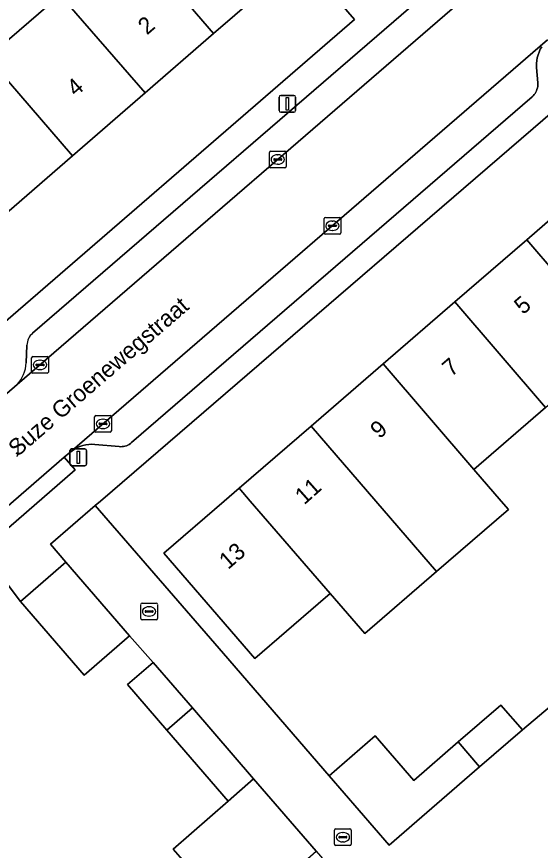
# Model space of a CAD drawing. Extents: x 160304 to 160955, y 383684 to 384161.
# Drawn here: x 160443.23 to 160474.6, y 383979.08 to 384029.01 of the extents above; entities that cross this region are included whole.
import ezdxf

# ---------------------------------------------------------------- set-up
doc = ezdxf.new("R2010")
doc.units = 0
for name, color, linetype in [('IMGEO_Erf', 7, 'Continuous'), ('IMGEO_Kolk', 7, 'Continuous'), ('IMGEO_Lichtmast', 7, 'Continuous'), ('IMGEO_Muur', 7, 'Continuous'), ('IMGEO_Openbare_ruimte_label', 7, 'Continuous'), ('IMGEO_Pand', 7, 'Continuous'), ('IMGEO_Pand_nummerreeks', 7, 'Continuous'), ('IMGEO_Parkeervlak_open', 7, 'Continuous'), ('IMGEO_Rijbaan_lokaal_open', 7, 'Continuous'), ('IMGEO_Rioolput', 7, 'Continuous'), ('IMGEO_Voetpad_open', 7, 'Continuous')]:
    doc.layers.add(name, color=color, linetype=linetype)

msp = doc.modelspace()

# ---------------------------------------------------------------- linework, layer by layer
at = {"layer": 'IMGEO_Erf'}
for points in [[(160423.895, 384030.632), (160426.46, 384027.667), (160424.932, 384026.345), (160440.174, 384008.722), (160463.456, 384028.84), (160460.261, 384032.534), (160455.025, 384028.001), (160450.924, 384024.45), (160446.57, 384020.681), (160442.307, 384016.99), (160437.953, 384013.22), (160432.866, 384019.096), (160436.647, 384022.369), (160437.219, 384022.865), (160441.483, 384026.556), (160445.837, 384030.325)], [(160480.946, 384028.137), (160448.239, 384000), (160447.932, 383999.736), (160455.612, 383990.866), (160461.946, 383983.55), (160464.706, 383985.939), (160467.017, 383983.269), (160469.682, 383985.571), (160472.239, 383987.78), (160473.521, 383986.297), (160476.215, 383988.562)], [(160474.915, 384005.61), (160470.61, 384001.896), (160472.246, 384000), (160472.684, 383999.492), (160468.376, 383995.775), (160464.074, 383992.064), (160462, 383994.468), (160461.279, 383993.846), (160457.495, 383990.577), (160452.051, 383996.881), (160455.662, 384000), (160456.556, 384000.772), (160460.864, 384004.492), (160465.175, 384008.216), (160469.478, 384011.932), (160473.784, 384015.651), (160478.09, 384019.371)], [(160456.376, 383974.841), (160452.604, 383979.153), (160455.89, 383982.028), (160452.212, 383986.286), (160449.864, 383989.004), (160451.404, 383990.334), (160449.988, 383991.923), (160447.265, 383989.57), (160443.455, 383993.98), (160442.593, 383995.12), (160425.555, 383980.472), (160425.435, 383978.53)]]:
    msp.add_lwpolyline(points, dxfattribs=at)
at = {"layer": 'IMGEO_Kolk'}
for p, q in [((160458.367, 384020.029), (160458.367, 384020.881)), ((160458.442, 384020.955), (160459.294, 384020.955)), ((160459.368, 384020.881), (160459.368, 384020.029)), ((160458.626, 384020.449), (160458.626, 384020.461)), ((160459.064, 384020.412), (160458.666, 384020.412)), ((160458.669, 384020.498), (160459.067, 384020.498)), ((160458.855, 384020.735), (160458.88, 384020.735)), ((160459.11, 384020.461), (160459.11, 384020.449)), ((160459.294, 384019.955), (160458.442, 384019.955)), ((160458.878, 384020.175), (160458.853, 384020.175)), ((160461.644, 384016.062), (160461.644, 384016.914)), ((160461.719, 384016.988), (160462.571, 384016.988)), ((160462.645, 384016.914), (160462.645, 384016.062)), ((160461.903, 384016.482), (160461.903, 384016.494)), ((160462.341, 384016.445), (160461.943, 384016.445)), ((160461.946, 384016.531), (160462.344, 384016.531)), ((160462.132, 384016.768), (160462.157, 384016.768)), ((160462.387, 384016.494), (160462.387, 384016.482)), ((160462.571, 384015.988), (160461.719, 384015.988)), ((160462.155, 384016.208), (160462.13, 384016.208)), ((160444.122, 384007.725), (160444.122, 384008.577)), ((160444.197, 384008.651), (160445.049, 384008.651)), ((160444.61, 384008.431), (160444.635, 384008.431)), ((160445.123, 384008.577), (160445.123, 384007.725)), ((160444.381, 384008.145), (160444.381, 384008.157)), ((160444.819, 384008.108), (160444.421, 384008.108)), ((160444.424, 384008.194), (160444.822, 384008.194)), ((160444.633, 384007.871), (160444.608, 384007.871)), ((160444.865, 384008.157), (160444.865, 384008.145)), ((160445.049, 384007.651), (160444.197, 384007.651)), ((160447.897, 384004.196), (160447.897, 384005.048)), ((160447.972, 384005.122), (160448.824, 384005.122)), ((160448.385, 384004.902), (160448.41, 384004.902)), ((160448.898, 384005.048), (160448.898, 384004.196)), ((160448.156, 384004.616), (160448.156, 384004.628)), ((160448.594, 384004.579), (160448.196, 384004.579)), ((160448.199, 384004.665), (160448.597, 384004.665)), ((160448.64, 384004.628), (160448.64, 384004.616)), ((160448.824, 384004.122), (160447.972, 384004.122)), ((160448.408, 384004.342), (160448.383, 384004.342)), ((160450.734, 383993.888), (160451.586, 383993.888)), ((160450.659, 383992.962), (160450.659, 383993.814)), ((160450.918, 383993.382), (160450.918, 383993.394)), ((160450.961, 383993.431), (160451.359, 383993.431)), ((160451.147, 383993.668), (160451.172, 383993.668)), ((160451.402, 383993.394), (160451.402, 383993.382)), ((160451.66, 383993.814), (160451.66, 383992.962)), ((160451.586, 383992.888), (160450.734, 383992.888)), ((160451.356, 383993.345), (160450.958, 383993.345)), ((160451.17, 383993.108), (160451.145, 383993.108)), ((160462.267, 383979.443), (160462.267, 383980.295)), ((160462.342, 383980.369), (160463.194, 383980.369)), ((160462.569, 383979.912), (160462.967, 383979.912)), ((160462.755, 383980.149), (160462.78, 383980.149)), ((160463.268, 383980.295), (160463.268, 383979.443)), ((160462.526, 383979.863), (160462.526, 383979.875)), ((160462.964, 383979.826), (160462.566, 383979.826)), ((160462.778, 383979.589), (160462.753, 383979.589)), ((160463.01, 383979.875), (160463.01, 383979.863)), ((160463.194, 383979.369), (160462.342, 383979.369))]:
    msp.add_line(p, q, dxfattribs=at)
for points in [[(160458.367, 384020.029), (160458.367, 384020.881)], [(160458.442, 384020.955), (160459.294, 384020.955)], [(160459.368, 384020.881), (160459.368, 384020.029)], [(160459.294, 384019.955), (160458.442, 384019.955)], [(160461.644, 384016.062), (160461.644, 384016.914)], [(160461.719, 384016.988), (160462.571, 384016.988)], [(160462.645, 384016.914), (160462.645, 384016.062)], [(160462.571, 384015.988), (160461.719, 384015.988)], [(160444.122, 384007.725), (160444.122, 384008.577)], [(160444.197, 384008.651), (160445.049, 384008.651)], [(160445.123, 384008.577), (160445.123, 384007.725)], [(160445.049, 384007.651), (160444.197, 384007.651)], [(160447.897, 384004.196), (160447.897, 384005.048)], [(160447.972, 384005.122), (160448.824, 384005.122)], [(160448.898, 384005.048), (160448.898, 384004.196)], [(160448.824, 384004.122), (160447.972, 384004.122)], [(160450.734, 383993.888), (160451.586, 383993.888)], [(160450.659, 383992.962), (160450.659, 383993.814)], [(160451.66, 383993.814), (160451.66, 383992.962)], [(160451.586, 383992.888), (160450.734, 383992.888)], [(160462.267, 383979.443), (160462.267, 383980.295)], [(160462.342, 383980.369), (160463.194, 383980.369)], [(160463.268, 383980.295), (160463.268, 383979.443)], [(160463.194, 383979.369), (160462.342, 383979.369)]]:
    msp.add_lwpolyline(points, dxfattribs=at)
for centre, radius, start, end in [((160458.444, 384020.879), 0.0765, 91.552, 178.448), ((160458.444, 384020.879), 0.0765, 91.552, 178.448), ((160459.292, 384020.879), 0.0765, 1.552, 88.448), ((160459.292, 384020.879), 0.0765, 1.552, 88.448), ((160458.666, 384020.458), 0.0403, 85.8775, 175.7526), ((160458.663, 384020.448), 0.0366, 178.938, 274.7102), ((160459.067, 384020.455), 0.043, 264.8664, 352.4533), ((160459.071, 384020.46), 0.0386, 1.7309, 96.639), ((160458.444, 384020.031), 0.0765, 181.552, 268.448), ((160458.444, 384020.031), 0.0765, 181.552, 268.448), ((160459.292, 384020.031), 0.0765, 271.552, 358.448), ((160459.292, 384020.031), 0.0765, 271.552, 358.448), ((160461.721, 384016.912), 0.0765, 91.552, 178.448), ((160461.721, 384016.912), 0.0765, 91.552, 178.448), ((160462.569, 384016.912), 0.0765, 1.552, 88.448), ((160462.569, 384016.912), 0.0765, 1.552, 88.448), ((160461.943, 384016.491), 0.0403, 85.8775, 175.7526), ((160461.94, 384016.481), 0.0366, 178.938, 274.7102), ((160462.344, 384016.488), 0.043, 264.8664, 352.4533), ((160462.348, 384016.493), 0.0386, 1.7309, 96.639), ((160461.721, 384016.064), 0.0765, 181.552, 268.448), ((160461.721, 384016.064), 0.0765, 181.552, 268.448), ((160462.569, 384016.064), 0.0765, 271.552, 358.448), ((160462.569, 384016.064), 0.0765, 271.552, 358.448), ((160444.199, 384008.575), 0.0765, 91.552, 178.448), ((160444.199, 384008.575), 0.0765, 91.552, 178.448), ((160445.047, 384008.575), 0.0765, 1.552, 88.448), ((160445.047, 384008.575), 0.0765, 1.552, 88.448), ((160444.421, 384008.154), 0.0403, 85.8775, 175.7526), ((160444.418, 384008.144), 0.0366, 178.938, 274.7102), ((160444.822, 384008.151), 0.043, 264.8664, 352.4533), ((160444.826, 384008.156), 0.0386, 1.7309, 96.639), ((160444.199, 384007.727), 0.0765, 181.552, 268.448), ((160444.199, 384007.727), 0.0765, 181.552, 268.448), ((160445.047, 384007.727), 0.0765, 271.552, 358.448), ((160445.047, 384007.727), 0.0765, 271.552, 358.448), ((160447.974, 384005.046), 0.0765, 91.552, 178.448), ((160447.974, 384005.046), 0.0765, 91.552, 178.448), ((160448.822, 384005.046), 0.0765, 1.552, 88.448), ((160448.822, 384005.046), 0.0765, 1.552, 88.448), ((160448.196, 384004.625), 0.0403, 85.8775, 175.7526), ((160448.193, 384004.615), 0.0366, 178.938, 274.7102), ((160448.597, 384004.622), 0.043, 264.8664, 352.4533), ((160448.601, 384004.627), 0.0386, 1.7309, 96.639), ((160447.974, 384004.198), 0.0765, 181.552, 268.448), ((160447.974, 384004.198), 0.0765, 181.552, 268.448), ((160448.822, 384004.198), 0.0765, 271.552, 358.448), ((160448.822, 384004.198), 0.0765, 271.552, 358.448), ((160450.736, 383993.812), 0.0765, 91.552, 178.448), ((160450.736, 383993.812), 0.0765, 91.552, 178.448), ((160451.584, 383993.812), 0.0765, 1.552, 88.448), ((160451.584, 383993.812), 0.0765, 1.552, 88.448), ((160450.958, 383993.391), 0.0403, 85.8775, 175.7526), ((160451.363, 383993.393), 0.0386, 1.7309, 96.639), ((160450.736, 383992.964), 0.0765, 181.552, 268.448), ((160450.736, 383992.964), 0.0765, 181.552, 268.448), ((160450.955, 383993.381), 0.0366, 178.938, 274.7102), ((160451.359, 383993.388), 0.043, 264.8664, 352.4533), ((160451.584, 383992.964), 0.0765, 271.552, 358.448), ((160451.584, 383992.964), 0.0765, 271.552, 358.448), ((160462.344, 383980.293), 0.0765, 91.552, 178.448), ((160462.344, 383980.293), 0.0765, 91.552, 178.448), ((160462.566, 383979.872), 0.0403, 85.8775, 175.7526), ((160462.971, 383979.874), 0.0386, 1.7309, 96.639), ((160463.192, 383980.293), 0.0765, 1.552, 88.448), ((160463.192, 383980.293), 0.0765, 1.552, 88.448), ((160462.344, 383979.445), 0.0765, 181.552, 268.448), ((160462.344, 383979.445), 0.0765, 181.552, 268.448), ((160462.563, 383979.862), 0.0366, 178.938, 274.7102), ((160462.967, 383979.869), 0.043, 264.8664, 352.4533), ((160463.192, 383979.445), 0.0765, 271.552, 358.448), ((160463.192, 383979.445), 0.0765, 271.552, 358.448)]:
    msp.add_arc(centre, radius, start, end, dxfattribs=at)
for centre, major_axis, ratio, start_param, end_param in [((160458.854, 384020.455), (-0.387, 0.002), 0.722429, 4.712389, 7.853982), ((160458.879, 384020.455), (-0.39, 0.002), 0.717154, 1.570796, 4.712389), ((160462.131, 384016.488), (-0.387, 0.002), 0.722429, 4.712389, 7.853982), ((160462.156, 384016.488), (-0.39, 0.002), 0.717154, 1.570796, 4.712389), ((160444.609, 384008.151), (-0.387, 0.002), 0.722429, 4.712389, 7.853982), ((160444.634, 384008.151), (-0.39, 0.002), 0.717154, 1.570796, 4.712389), ((160448.384, 384004.622), (-0.387, 0.002), 0.722429, 4.712389, 7.853982), ((160448.409, 384004.622), (-0.39, 0.002), 0.717154, 1.570796, 4.712389), ((160451.146, 383993.388), (-0.387, 0.002), 0.722429, 4.712389, 7.853982), ((160451.171, 383993.388), (-0.39, 0.002), 0.717154, 1.570796, 4.712389), ((160462.754, 383979.869), (-0.387, 0.002), 0.722429, 4.712389, 7.853982), ((160462.779, 383979.869), (-0.39, 0.002), 0.717154, 1.570796, 4.712389)]:
    msp.add_ellipse(centre, major_axis=major_axis, ratio=ratio, start_param=start_param, end_param=end_param, dxfattribs=at)
at = {"layer": 'IMGEO_Lichtmast'}
for p, q in [((160458.948, 384023.389), (160458.948, 384024.189)), ((160458.948, 384024.189), (160458.948, 384023.389)), ((160459.048, 384024.289), (160459.838, 384024.289)), ((160459.838, 384024.289), (160459.048, 384024.289)), ((160459.938, 384024.189), (160459.938, 384023.389)), ((160459.938, 384023.389), (160459.938, 384024.189)), ((160459.838, 384023.289), (160459.048, 384023.289)), ((160459.048, 384023.289), (160459.838, 384023.289)), ((160446.42, 384002.217), (160446.42, 384003.017)), ((160446.42, 384003.017), (160446.42, 384002.217)), ((160446.52, 384003.117), (160447.31, 384003.117)), ((160447.31, 384003.117), (160446.52, 384003.117)), ((160447.41, 384003.017), (160447.41, 384002.217)), ((160447.41, 384002.217), (160447.41, 384003.017)), ((160447.31, 384002.117), (160446.52, 384002.117)), ((160446.52, 384002.117), (160447.31, 384002.117))]:
    msp.add_line(p, q, dxfattribs=at)
for points in [[(160459.368, 384024.164), (160459.518, 384024.164), (160459.518, 384023.414), (160459.368, 384023.414), (160459.368, 384024.164)], [(160446.84, 384002.992), (160446.99, 384002.992), (160446.99, 384002.242), (160446.84, 384002.242), (160446.84, 384002.992)]]:
    msp.add_lwpolyline(points, dxfattribs=at)
for centre, start, end in [((160459.048, 384024.189), 90, 180), ((160459.048, 384024.189), 90, 180), ((160459.838, 384024.189), 0, 90), ((160459.838, 384024.189), 360, 90), ((160459.048, 384023.389), 180, 270), ((160459.048, 384023.389), 180, 270), ((160459.838, 384023.389), 270, 0), ((160459.838, 384023.389), 270, 0), ((160446.52, 384003.017), 90, 180), ((160446.52, 384003.017), 90, 180), ((160447.31, 384003.017), 0, 90), ((160447.31, 384003.017), 360, 90), ((160446.52, 384002.217), 180, 270), ((160446.52, 384002.217), 180, 270), ((160447.31, 384002.217), 270, 0), ((160447.31, 384002.217), 270, 0)]:
    msp.add_arc(centre, 0.1, start, end, dxfattribs=at)
at = {"layer": 'IMGEO_Muur'}
msp.add_lwpolyline([(160461.946, 383983.55), (160455.612, 383990.866)], dxfattribs=at)
at = {"layer": 'IMGEO_Pand'}
for points in [[(160463.097, 384036.252), (160463.23, 384038.097), (160463.324, 384039.406), (160461.083, 384041.994), (160458.283, 384045.229), (160452.287, 384040.18), (160454.4, 384037.739), (160449.944, 384033.881), (160455.025, 384028.001), (160460.261, 384032.534), (160463, 384034.905)], [(160445.837, 384030.325), (160450.924, 384024.45), (160455.025, 384028.001), (160449.944, 384033.881)], [(160445.837, 384030.325), (160441.483, 384026.556), (160446.57, 384020.681), (160450.924, 384024.45)], [(160437.219, 384022.865), (160442.307, 384016.99), (160446.57, 384020.681), (160441.483, 384026.556)], [(160483.531, 384013.043), (160478.09, 384019.371), (160473.784, 384015.651), (160479.25, 384009.3), (160481.518, 384006.62), (160485.849, 384010.356), (160485.647, 384010.59)], [(160481.518, 384006.62), (160479.25, 384009.3), (160473.784, 384015.651), (160469.478, 384011.932), (160474.915, 384005.61), (160477.59, 384007.917), (160479.908, 384005.23)], [(160465.175, 384008.216), (160470.61, 384001.896), (160474.915, 384005.61), (160469.478, 384011.932)], [(160468.376, 383995.775), (160472.684, 383999.492), (160472.246, 384000), (160470.61, 384001.896), (160465.175, 384008.216), (160460.864, 384004.492), (160464.735, 384000)], [(160456.556, 384000.772), (160457.223, 384000), (160462, 383994.468), (160464.074, 383992.064), (160468.376, 383995.775), (160464.735, 384000), (160460.864, 384004.492)], [(160456.556, 384000.772), (160455.662, 384000), (160452.051, 383996.881), (160457.495, 383990.577), (160461.279, 383993.846), (160462, 383994.468), (160457.223, 384000)], [(160446.178, 383996.332), (160443.455, 383993.98), (160447.265, 383989.57), (160449.988, 383991.923)], [(160452.212, 383986.286), (160453.75, 383987.619), (160451.404, 383990.334), (160449.864, 383989.004)], [(160452.212, 383986.286), (160455.89, 383982.028), (160457.423, 383983.369), (160453.75, 383987.619)], [(160469.682, 383985.571), (160470.963, 383984.088), (160473.521, 383986.297), (160472.239, 383987.78)], [(160469.682, 383985.571), (160467.017, 383983.269), (160464.706, 383985.939), (160461.946, 383983.55), (160465.537, 383979.401), (160470.963, 383984.088)], [(160457.423, 383983.369), (160455.89, 383982.028), (160452.604, 383979.153), (160456.376, 383974.841), (160459.641, 383977.685), (160461.178, 383979.024)]]:
    msp.add_lwpolyline(points, close=True, dxfattribs=at)
at = {"layer": 'IMGEO_Parkeervlak_open'}
for points in [[(160443.247, 384006.975), (160471.504, 384031.385)], [(160468.436, 384031.002), (160444.182, 384010.054)], [(160475.034, 384027.614), (160446.417, 384002.912), (160446.543, 384003.012), (160446.694, 384003.111), (160446.853, 384003.197), (160447.019, 384003.268), (160447.19, 384003.324), (160447.366, 384003.365), (160447.545, 384003.389), (160447.725, 384003.398), (160447.905, 384003.39), (160449.361, 384003.258), (160449.45, 384003.254), (160449.539, 384003.257), (160449.627, 384003.269), (160449.714, 384003.288), (160449.799, 384003.316), (160449.882, 384003.35), (160449.96, 384003.392), (160450.035, 384003.441), (160450.105, 384003.496), (160474.103, 384024.212), (160474.168, 384024.273), (160474.227, 384024.34), (160474.28, 384024.412), (160474.327, 384024.488), (160474.366, 384024.568), (160474.398, 384024.652), (160474.423, 384024.738), (160474.44, 384024.826), (160474.449, 384024.914), (160474.45, 384025.004), (160474.447, 384025.048), (160474.374, 384025.967), (160474.37, 384026.02), (160474.369, 384026.198), (160474.384, 384026.376), (160474.414, 384026.552), (160474.46, 384026.725), (160474.521, 384026.892), (160474.597, 384027.054), (160474.687, 384027.208)], [(160443.837, 384009.335), (160443.797, 384008.278)]]:
    msp.add_lwpolyline(points, dxfattribs=at)
for centre, radius, start, end in [((160444.841, 384009.296), 1.005, 130.9806, 177.7529), ((160441.8, 384008.354), 1.999, 316.3963, 357.8343)]:
    msp.add_arc(centre, radius, start, end, dxfattribs=at)
at = {"layer": 'IMGEO_Rijbaan_lokaal_open'}
for points in [[(160484.061, 384038.186), (160473.972, 384034.203), (160473.91, 384034.061), (160473.654, 384033.596), (160473.358, 384033.154), (160473.024, 384032.741), (160472.654, 384032.36), (160472.252, 384032.013), (160471.504, 384031.385), (160443.247, 384006.975), (160442.642, 384006.44), (160439.545, 384003.767), (160435.187, 384000), (160424.255, 383990.462), (160420.449, 383987.142), (160422.038, 383985.305), (160423.775, 383983.297), (160425.096, 383984.442), (160439.728, 383997.125), (160440.231, 383997.562), (160443.044, 384000), (160446.077, 384002.618), (160446.417, 384002.912), (160475.034, 384027.614)], [(160476.215, 383988.562), (160473.521, 383986.297), (160470.963, 383984.088), (160465.537, 383979.401), (160461.946, 383983.55), (160455.612, 383990.866), (160447.932, 383999.736), (160445.259, 383997.425), (160446.178, 383996.332), (160449.988, 383991.923), (160451.404, 383990.334), (160453.75, 383987.619), (160457.423, 383983.369), (160461.178, 383979.024), (160463.398, 383976.454), (160464.919, 383974.746), (160465.76, 383975.48), (160467.199, 383973.824), (160469.555, 383971.096), (160471.72, 383968.59), (160474.132, 383965.766), (160476.935, 383966.864)]]:
    msp.add_lwpolyline(points, dxfattribs=at)
at = {"layer": 'IMGEO_Rioolput'}
msp.add_line((160443.299, 384003.612), (160443.299, 384002.76), dxfattribs=at)
msp.add_lwpolyline([(160443.299, 384003.612), (160443.299, 384002.76)], dxfattribs=at)
for centre, start, end in [((160443.223, 384003.61), 1.552, 88.448), ((160443.223, 384003.61), 1.552, 88.448), ((160443.223, 384002.762), 271.552, 358.448), ((160443.223, 384002.762), 271.552, 358.448)]:
    msp.add_arc(centre, 0.0765, start, end, dxfattribs=at)
at = {"layer": 'IMGEO_Voetpad_open'}
for points in [[(160460.261, 384032.534), (160463.456, 384028.84), (160440.174, 384008.722), (160437.655, 384006.413), (160434.935, 384004.073), (160429.993, 384000), (160418.503, 383989.954), (160420.449, 383987.142), (160424.255, 383990.462)], [(160444.182, 384010.054), (160468.436, 384031.002)], [(160442.593, 383995.12), (160443.455, 383993.98), (160446.178, 383996.332), (160445.259, 383997.425), (160447.932, 383999.736), (160448.239, 384000), (160480.946, 384028.137)], [(160474.687, 384027.208), (160474.597, 384027.054), (160474.521, 384026.892), (160474.46, 384026.725), (160474.414, 384026.552), (160474.384, 384026.376), (160474.369, 384026.198), (160474.37, 384026.02), (160474.374, 384025.967), (160474.447, 384025.048), (160474.45, 384025.004), (160474.449, 384024.914), (160474.44, 384024.826), (160474.423, 384024.738), (160474.398, 384024.652), (160474.366, 384024.568), (160474.327, 384024.488), (160474.28, 384024.412), (160474.227, 384024.34), (160474.168, 384024.273), (160474.103, 384024.212), (160450.105, 384003.496), (160450.035, 384003.441), (160449.96, 384003.392), (160449.882, 384003.35), (160449.799, 384003.316), (160449.714, 384003.288), (160449.627, 384003.269), (160449.539, 384003.257), (160449.45, 384003.254), (160449.361, 384003.258), (160447.905, 384003.39), (160447.725, 384003.398), (160447.545, 384003.389), (160447.366, 384003.365), (160447.19, 384003.324), (160447.019, 384003.268), (160446.853, 384003.197), (160446.694, 384003.111), (160446.543, 384003.012), (160446.417, 384002.912), (160446.077, 384002.618), (160446.732, 384001.862), (160440.886, 383996.806)], [(160443.797, 384008.278), (160443.837, 384009.335)], [(160439.545, 384003.767), (160438.892, 384004.525), (160441.989, 384007.198), (160442.642, 384006.44), (160443.247, 384006.975)]]:
    msp.add_lwpolyline(points, dxfattribs=at)
msp.add_lwpolyline([(160440.231, 383997.562), (160440.886, 383996.806), (160446.732, 384001.862), (160446.077, 384002.618), (160443.044, 384000)], close=True, dxfattribs=at)
for centre, radius, start, end in [((160444.841, 384009.296), 1.005, 130.9806, 177.7529), ((160441.8, 384008.354), 1.999, 316.3963, 357.8343)]:
    msp.add_arc(centre, radius, start, end, dxfattribs=at)

# ---------------------------------------------------------------- texts
at = {"layer": 'IMGEO_Openbare_ruimte_label'}
msp.add_text('Suze Groenewegstraat', height=1, rotation=40.7816, dxfattribs=at).set_placement((160443.263, 384002.61))
at = {"layer": 'IMGEO_Pand_nummerreeks'}
for s, rotation, p in [('2', 40.8863, (160451.032, 384027.877)), ('4', 40.8863, (160446.765, 384024.183)), ('5', 40.8175, (160473.567, 384011.128)), ('7', 40.8175, (160469.26, 384007.409)), ('9', 40.8175, (160464.953, 384003.689)), ('11', 41.6368, (160460.453, 383999.738)), ('13', 40.8175, (160455.891, 383995.863))]:
    msp.add_text(s, height=1, rotation=rotation, dxfattribs=at).set_placement(p)

doc.saveas('drawing.dxf')
